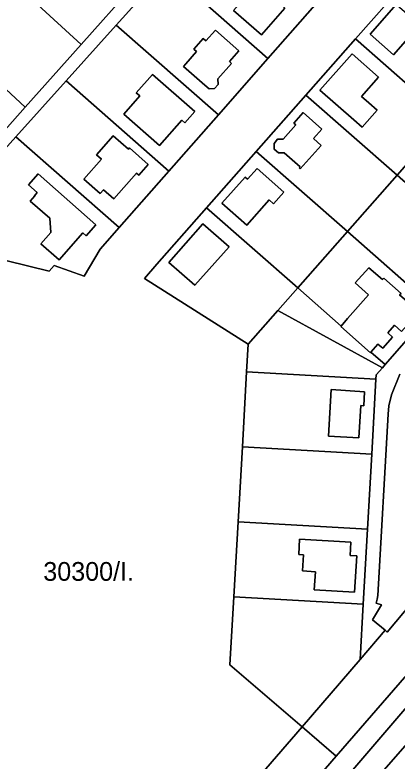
# Model space of a CAD drawing. Extents: x -537068 to -534056, y -1176840 to -1172401.
# Drawn here: x -536242.4 to -536140.7, y -1175956.9 to -1175758.1 of the extents above; entities that cross this region are included whole.
import ezdxf

# ---------------------------------------------------------------- set-up
doc = ezdxf.new("R2010")
doc.units = 0
for name, color, linetype in [('95560013', 7, 'Continuous'), ('95590013', 7, 'Continuous'), ('95610013', 7, 'Continuous'), ('95640013', 7, 'Continuous'), ('95660013', 7, 'Continuous')]:
    doc.layers.add(name, color=color, linetype=linetype)

msp = doc.modelspace()

# ---------------------------------------------------------------- linework, layer by layer
at = {"layer": '95560013'}
for points in [[(-536188.68, -1175731.06), (-536161.83, -1175754.68), (-536175.04, -1175769.7), (-536202.05, -1175745.94)], [(-536188.25, -1175784.71), (-536215.42, -1175760.82), (-536202.05, -1175745.94), (-536175.04, -1175769.7)], [(-536176.8, -1175763.42), (-536170.53, -1175756.32), (-536172.62, -1175754.46), (-536170.28, -1175751.82), (-536176.73, -1175746.11), (-536179.29, -1175749), (-536178.17, -1175750), (-536184.22, -1175756.87)], [(-536114.26, -1175770.77), (-536127.47, -1175785.79), (-536151.76, -1175764.43), (-536138.55, -1175749.41)], [(-536134.64, -1175760.77), (-536134.83, -1175760.58), (-536132.67, -1175758.08), (-536138.46, -1175753.02), (-536140.66, -1175755.49), (-536140.88, -1175755.31), (-536147.84, -1175763.26), (-536141.65, -1175768.71)], [(-536215.42, -1175760.82), (-536188.25, -1175784.71), (-536201.46, -1175799.73), (-536228.79, -1175775.69)], [(-536194.06, -1175767.88), (-536196.87, -1175771.08), (-536197.53, -1175771.85), (-536191.84, -1175776.85), (-536190.73, -1175777.82), (-536189.29, -1175777.7), (-536188.34, -1175776.6), (-536188.39, -1175775.16), (-536184.74, -1175771), (-536185.31, -1175770.51), (-536182.81, -1175767.66), (-536189.03, -1175762.16), (-536191.54, -1175765.02), (-536192.28, -1175764.36), (-536194.79, -1175767.22)], [(-536151.76, -1175764.43), (-536127.47, -1175785.79), (-536140.68, -1175800.81), (-536164.97, -1175779.44)], [(-536161.19, -1175778.16), (-536152.2, -1175786.06), (-536149.97, -1175788.01), (-536145.98, -1175783.44), (-536148.17, -1175781.5), (-536150.1, -1175779.8), (-536145.59, -1175774.66), (-536152.66, -1175768.45)], [(-536203.92, -1175792.9), (-536197.95, -1175786.11), (-536197.13, -1175786.82), (-536194.53, -1175783.83), (-536205.77, -1175773.96), (-536210.09, -1175778.87), (-536209.12, -1175779.67), (-536213.43, -1175784.57)], [(-536228.79, -1175775.69), (-536201.46, -1175799.73), (-536214.67, -1175814.75), (-536242.16, -1175790.56)], [(-536178.18, -1175794.46), (-536164.97, -1175779.44), (-536140.68, -1175800.81), (-536153.89, -1175815.83)], [(-536173.42, -1175792.38), (-536173.37, -1175793.85), (-536172.23, -1175794.85), (-536170.71, -1175794.82), (-536166.5, -1175798.58), (-536166.73, -1175798.87), (-536166.43, -1175799.13), (-536160.85, -1175792.87), (-536162.93, -1175791.04), (-536160.67, -1175788.49), (-536165.68, -1175784.07), (-536168.19, -1175786.92), (-536167.65, -1175787.41), (-536171.01, -1175791.19), (-536172.47, -1175791.19)], [(-536127.47, -1175785.79), (-536104.24, -1175806.23), (-536117.45, -1175821.25), (-536140.68, -1175800.81)], [(-536209.46, -1175800.8), (-536206.91, -1175797.92), (-536211.9, -1175793.47), (-536212.21, -1175793.82), (-536216.21, -1175790.28), (-536220.67, -1175795.33), (-536219.32, -1175796.53), (-536224.03, -1175801.85), (-536219.72, -1175805.64), (-536218.83, -1175804.69), (-536216.06, -1175807.12), (-536210.06, -1175800.3)], [(-536167.1, -1175830.84), (-536191.39, -1175809.48), (-536178.18, -1175794.46), (-536153.89, -1175815.83)], [(-536180.45, -1175801.89), (-536181.14, -1175801.29), (-536187.29, -1175808.27), (-536180.67, -1175814.1), (-536174.73, -1175807.36), (-536173.53, -1175808.41), (-536170.78, -1175805.28), (-536177.91, -1175799)], [(-536153.89, -1175815.83), (-536140.68, -1175800.81), (-536117.45, -1175821.25), (-536130.66, -1175836.27)], [(-536191.39, -1175809.48), (-536167.1, -1175830.84), (-536172.38, -1175836.84), (-536180.31, -1175845.86), (-536207.91, -1175828.28), (-536204.6, -1175824.5)], [(-536185.4, -1175819.91), (-536192.35, -1175813.79), (-536201.39, -1175824.04), (-536194.51, -1175830.1)], [(-536139.45, -1175842.47), (-536134.83, -1175837.25), (-536139.99, -1175832.71), (-536139.62, -1175832.31), (-536144.23, -1175828.21), (-536144.56, -1175828.58), (-536148.15, -1175825.44), (-536151.81, -1175829.49), (-536148.24, -1175832.66), (-536153.86, -1175839.01), (-536155.53, -1175841.02), (-536167.1, -1175830.84), (-536153.89, -1175815.83), (-536130.66, -1175836.27), (-536143.87, -1175851.28), (-536147.64, -1175847.96), (-536145.76, -1175845.8), (-536144.49, -1175846.9), (-536141.9, -1175843.92), (-536143.17, -1175842.81), (-536141.36, -1175840.78)], [(-536143.87, -1175851.28), (-536144.59, -1175852.11), (-536172.38, -1175836.84), (-536167.1, -1175830.84), (-536155.53, -1175841.02), (-536155.6, -1175841.1), (-536147.76, -1175848.1), (-536147.64, -1175847.96)], [(-536146.22, -1175853.97), (-536146.29, -1175855.17), (-536180.73, -1175853.21), (-536180.31, -1175845.86), (-536172.38, -1175836.84), (-536144.59, -1175852.11)], [(-536146.29, -1175855.17), (-536147.42, -1175875.13), (-536181.86, -1175873.18), (-536180.73, -1175853.21)], [(-536149.3, -1175858.48), (-536158.18, -1175857.94), (-536158.9, -1175870.34), (-536150.82, -1175870.82), (-536150.32, -1175862.2), (-536149.53, -1175862.27)], [(-536125.4, -1175919.17), (-536104.79, -1175894.1), (-536100.8, -1175889.37), (-536087.89, -1175874.08), (-536074.99, -1175858.81), (-536074.44, -1175858.16), (-536072.55, -1175864.43), (-536090.43, -1175886.34), (-536122.67, -1175924.43), (-536168.94, -1175978.56), (-536221.04, -1176039.38), (-536225.71, -1176034.45), (-536173.33, -1175974.59), (-536156.87, -1175955.6), (-536127.54, -1175921.77)], [(-536168.94, -1175978.56), (-536122.67, -1175924.43), (-536090.43, -1175886.34), (-536072.55, -1175864.43), (-536070.38, -1175871.62), (-536110.29, -1175920.61), (-536163.59, -1175981.53), (-536188.09, -1176010.56), (-536217.36, -1176043.27), (-536221.04, -1176039.38)], [(-536163.59, -1175981.53), (-536110.29, -1175920.61), (-536070.38, -1175871.62), (-536067.83, -1175880.11), (-536098.45, -1175916.42), (-536131.18, -1175954.95), (-536189.54, -1176022.76), (-536212.9, -1176048.06), (-536213.13, -1176047.73), (-536217.36, -1176043.27), (-536188.09, -1176010.56)], [(-536148.56, -1175895.1), (-536183, -1175893.14), (-536181.86, -1175873.18), (-536147.42, -1175875.13)], [(-536184.13, -1175913.11), (-536183, -1175893.14), (-536148.56, -1175895.1), (-536149.69, -1175915.07)], [(-536166.86, -1175901.89), (-536165.58, -1175901.97), (-536165.85, -1175906.25), (-536162.42, -1175906.47), (-536162.72, -1175911.27), (-536151.99, -1175911.89), (-536151.41, -1175902.21), (-536153.14, -1175902.11), (-536152.94, -1175898.57), (-536166.62, -1175897.77)], [(-536143.3, -1175922.54), (-536134.11, -1175911.51), (-536125.4, -1175919.17), (-536127.54, -1175921.77), (-536156.87, -1175955.6), (-536165.96, -1175947.78), (-536150.53, -1175929.84), (-536143.86, -1175922.07)], [(-536184.13, -1175913.11), (-536149.69, -1175915.07), (-536150.53, -1175929.84), (-536165.96, -1175947.78), (-536185.16, -1175931.26)], [(-536165.96, -1175947.78), (-536156.87, -1175955.6), (-536173.33, -1175974.59), (-536225.71, -1176034.45), (-536226.33, -1176033.8), (-536231.96, -1176024.21)]]:
    msp.add_lwpolyline(points, close=True, dxfattribs=at)
for points in [[(-536138.55, -1175749.41), (-536151.76, -1175764.43), (-536164.97, -1175779.44), (-536178.18, -1175794.46), (-536191.39, -1175809.48), (-536204.6, -1175824.5), (-536207.91, -1175828.28), (-536180.31, -1175845.86), (-536180.73, -1175853.21), (-536181.86, -1175873.18), (-536183, -1175893.14), (-536184.13, -1175913.11), (-536185.16, -1175931.26), (-536165.96, -1175947.78), (-536231.96, -1176024.21)], [(-536266.93, -1175818.13), (-536233.28, -1175826.33), (-536231.95, -1175824.82), (-536223.98, -1175827.73), (-536219.75, -1175820.53), (-536214.67, -1175814.75), (-536201.46, -1175799.73), (-536188.25, -1175784.71), (-536175.04, -1175769.7), (-536161.83, -1175754.68)], [(-536139.95, -1175853.82), (-536142.19, -1175859.34), (-536142.82, -1175862.21), (-536143.07, -1175864.44), (-536145.78, -1175912.79), (-536145.96, -1175913.78), (-536146.26, -1175914.83), (-536144.84, -1175915.24), (-536147.21, -1175919.29), (-536143.86, -1175922.07), (-536150.53, -1175929.84), (-536149.69, -1175915.07), (-536148.56, -1175895.1), (-536147.42, -1175875.13), (-536146.29, -1175855.17), (-536146.22, -1175853.97), (-536144.59, -1175852.11), (-536143.87, -1175851.28), (-536130.66, -1175836.27)]]:
    msp.add_lwpolyline(points, dxfattribs=at)
at = {"layer": '95590013'}
for points in [[(-536336.86, -1175651.81), (-536328.47, -1175643.22), (-536210.86, -1175750.28), (-536224.74, -1175766), (-536318.84, -1175679.8), (-536342.66, -1175658.34)], [(-536318.84, -1175679.8), (-536224.74, -1175766), (-536239.66, -1175782.64), (-536332.34, -1175696.33)], [(-536246.52, -1175790.3), (-536351.63, -1175691.34), (-536345.16, -1175684.67), (-536339.99, -1175689.2), (-536332.34, -1175696.33), (-536239.66, -1175782.64)]]:
    msp.add_lwpolyline(points, close=True, dxfattribs=at)
at = {"layer": '95610013'}
for points in [[(-536262.79, -1175813.53), (-536242.16, -1175790.56), (-536214.67, -1175814.75), (-536219.75, -1175820.53), (-536223.98, -1175827.73), (-536231.95, -1175824.82), (-536233.28, -1175826.33), (-536266.93, -1175818.13)], [(-536235.5, -1175819.08), (-536230.64, -1175823.33), (-536224.33, -1175816.15), (-536223.42, -1175816.96), (-536220.82, -1175814), (-536236.23, -1175800.4), (-536238.83, -1175803.35), (-536236.49, -1175805.41), (-536237.23, -1175806.26), (-536237.14, -1175806.32), (-536238.33, -1175807.71), (-536233.12, -1175812.29), (-536232.88, -1175816.09)]]:
    msp.add_lwpolyline(points, close=True, dxfattribs=at)
at = {"layer": '95640013'}
for points in [[(-536246.52, -1175790.3), (-536239.66, -1175782.64), (-536224.74, -1175766), (-536210.86, -1175750.28), (-536196.66, -1175734.2), (-536189.71, -1175726.32), (-536182.76, -1175718.44), (-536169.27, -1175703.26), (-536165.13, -1175696.86), (-536161.26, -1175700.56), (-536175.31, -1175716.19), (-536188.68, -1175731.06), (-536202.05, -1175745.94), (-536215.42, -1175760.82), (-536228.79, -1175775.69), (-536242.16, -1175790.56), (-536262.79, -1175813.53)], [(-536134.11, -1175911.51), (-536143.3, -1175922.54), (-536143.86, -1175922.07), (-536147.21, -1175919.29), (-536144.84, -1175915.24), (-536146.26, -1175914.83), (-536145.96, -1175913.78), (-536145.78, -1175912.79), (-536143.07, -1175864.44), (-536142.82, -1175862.21), (-536142.19, -1175859.34), (-536139.95, -1175853.82)]]:
    msp.add_lwpolyline(points, dxfattribs=at)
for points in [[(-536184.22, -1175756.87), (-536178.17, -1175750), (-536179.29, -1175749), (-536176.73, -1175746.11), (-536170.28, -1175751.82), (-536172.62, -1175754.46), (-536170.53, -1175756.32), (-536176.8, -1175763.42)], [(-536140.88, -1175755.31), (-536140.66, -1175755.49), (-536134.83, -1175760.58), (-536134.64, -1175760.77), (-536141.65, -1175768.71), (-536147.84, -1175763.26)], [(-536188.39, -1175775.16), (-536188.34, -1175776.6), (-536189.29, -1175777.7), (-536190.73, -1175777.82), (-536191.84, -1175776.85), (-536197.53, -1175771.85), (-536196.87, -1175771.08), (-536194.06, -1175767.88), (-536194.79, -1175767.22), (-536192.28, -1175764.36), (-536191.54, -1175765.02), (-536189.03, -1175762.16), (-536182.81, -1175767.66), (-536185.31, -1175770.51), (-536184.74, -1175771)], [(-536145.98, -1175783.44), (-536149.97, -1175788.01), (-536152.2, -1175786.06), (-536161.19, -1175778.16), (-536152.66, -1175768.45), (-536145.59, -1175774.66), (-536150.1, -1175779.8), (-536148.17, -1175781.5)], [(-536205.77, -1175773.96), (-536194.53, -1175783.83), (-536197.13, -1175786.82), (-536197.95, -1175786.11), (-536203.92, -1175792.9), (-536213.43, -1175784.57), (-536209.12, -1175779.67), (-536210.09, -1175778.87)], [(-536160.67, -1175788.49), (-536162.93, -1175791.04), (-536160.85, -1175792.87), (-536166.43, -1175799.13), (-536166.73, -1175798.87), (-536166.5, -1175798.58), (-536170.71, -1175794.82), (-536172.23, -1175794.85), (-536173.37, -1175793.85), (-536173.42, -1175792.38), (-536172.47, -1175791.19), (-536171.01, -1175791.19), (-536167.65, -1175787.41), (-536168.19, -1175786.92), (-536165.68, -1175784.07)], [(-536219.32, -1175796.53), (-536220.67, -1175795.33), (-536216.21, -1175790.28), (-536212.21, -1175793.82), (-536211.9, -1175793.47), (-536206.91, -1175797.92), (-536209.46, -1175800.8), (-536210.06, -1175800.3), (-536216.06, -1175807.12), (-536218.83, -1175804.69), (-536219.72, -1175805.64), (-536224.03, -1175801.85)], [(-536224.33, -1175816.15), (-536230.64, -1175823.33), (-536235.5, -1175819.08), (-536232.88, -1175816.09), (-536233.12, -1175812.29), (-536238.33, -1175807.71), (-536237.14, -1175806.32), (-536237.23, -1175806.26), (-536236.49, -1175805.41), (-536238.83, -1175803.35), (-536236.23, -1175800.4), (-536220.82, -1175814), (-536223.42, -1175816.96)], [(-536174.73, -1175807.36), (-536180.67, -1175814.1), (-536187.29, -1175808.27), (-536181.14, -1175801.29), (-536180.45, -1175801.89), (-536177.91, -1175799), (-536170.78, -1175805.28), (-536173.53, -1175808.41)], [(-536192.35, -1175813.79), (-536185.4, -1175819.91), (-536194.51, -1175830.1), (-536201.39, -1175824.04)], [(-536155.6, -1175841.1), (-536155.53, -1175841.02), (-536153.86, -1175839.01), (-536148.24, -1175832.66), (-536151.81, -1175829.49), (-536148.15, -1175825.44), (-536144.56, -1175828.58), (-536144.23, -1175828.21), (-536139.62, -1175832.31), (-536139.99, -1175832.71), (-536134.83, -1175837.25), (-536139.45, -1175842.47), (-536141.36, -1175840.78), (-536143.17, -1175842.81), (-536141.9, -1175843.92), (-536144.49, -1175846.9), (-536145.76, -1175845.8), (-536147.64, -1175847.96), (-536147.76, -1175848.1)], [(-536158.18, -1175857.94), (-536149.3, -1175858.48), (-536149.53, -1175862.27), (-536150.32, -1175862.2), (-536150.82, -1175870.82), (-536158.9, -1175870.34)], [(-536151.99, -1175911.89), (-536162.72, -1175911.27), (-536162.42, -1175906.47), (-536165.85, -1175906.25), (-536165.58, -1175901.97), (-536166.86, -1175901.89), (-536166.62, -1175897.77), (-536152.94, -1175898.57), (-536153.14, -1175902.11), (-536151.41, -1175902.21)]]:
    msp.add_lwpolyline(points, close=True, dxfattribs=at)

# ---------------------------------------------------------------- texts
at = {"layer": '95660013'}
msp.add_text('30300/I.', height=5, rotation=0, dxfattribs=at).set_placement((-536234.86, -1175908.88))

doc.saveas('drawing.dxf')
